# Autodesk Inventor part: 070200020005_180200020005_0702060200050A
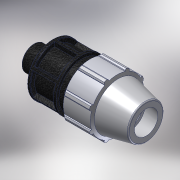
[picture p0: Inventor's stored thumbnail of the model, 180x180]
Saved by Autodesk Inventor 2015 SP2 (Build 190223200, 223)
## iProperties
Created: 2017-02
Part Number: 070200020005_180200020005_0702060200050A
Material: PVC-Piping
Description: PLASSON MALE ADAPTOR 20-1/2"
Document SubType Name: Modeling
Designer: KIM
Mass: 92.6774 g
Surface Area: 199.44 cm^2
Volume: 66.1981 cm^3
Density: 1.4 g/cm^3
Appearance: PTFE
Author: KIM
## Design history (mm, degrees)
derived "07020.ipt"
feature "Solid1::07020.ipt"
tag "TaggingFeature1"
body "Solid1"
other parameters: "d4" = 13.14286, "d5" = 23, "d7" = 48, "d8" = 36, "d9" = 13.14286, "d11" = 2.62857, "d12" = 38.4, "d13" = 120 deg, "d15" = 12 deg, "d16" = 43.2, "d18" = 1, "d19" = 35 deg, "d20" = 17.5 deg, "d21" = 44.64, "d23" = 0, "d25" = 360 deg, "d27" = 0.96, "d34" = 2.4, "d36" = 0, "d42" = 23, "d43" = 1.44, "d46" = 0.6, "d49" = 71, "d51" = 92, "d52" = 17, "d53" = 0.4, "d55" = 360 deg, "d57" = 20.955, "d58" = 14.6685, "d59" = 18.4, "E_" = 48, "H_" = 92, "l_" = 71, "l_2" = 17, "R_" = 20.955
